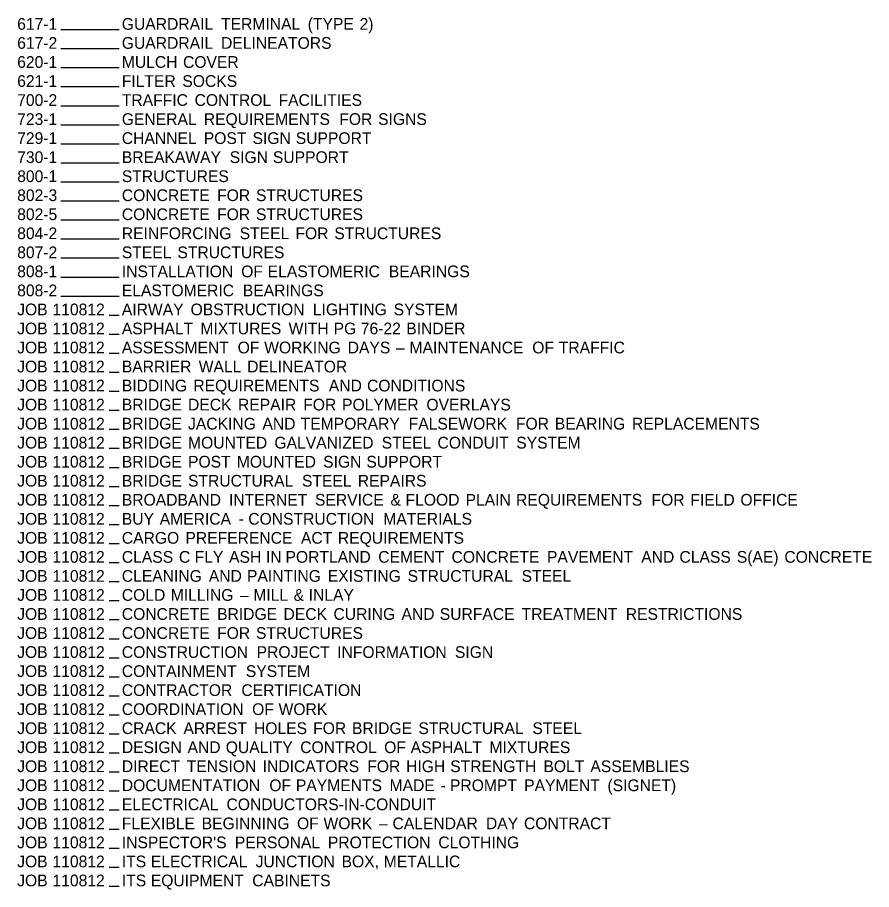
# Model space of a CAD drawing. Extents: x 200 to 2094, y 35 to 1167.
# Drawn here: x 200.8 to 638.5, y 88.4 to 535.1 of the extents above; entities that cross this region are included whole.
import ezdxf

# ---------------------------------------------------------------- set-up
doc = ezdxf.new("R2010")
doc.units = 0
doc.layers.add('Default', color=7, linetype='Continuous')

msp = doc.modelspace()

# ---------------------------------------------------------------- linework, layer by layer
at = {"layer": 'Default'}
for p, q in [((252.93, 528.73), (223.08, 528.73)), ((252.93, 518.98), (223.08, 518.98)), ((252.93, 509.23), (223.08, 509.23)), ((252.93, 499.48), (223.08, 499.48)), ((252.93, 489.73), (223.08, 489.73)), ((252.93, 479.98), (223.08, 479.98)), ((252.93, 470.23), (223.08, 470.23)), ((252.93, 460.48), (223.08, 460.48)), ((252.93, 450.73), (223.08, 450.73)), ((252.93, 440.98), (223.08, 440.98)), ((252.93, 431.23), (223.08, 431.23)), ((252.93, 421.48), (223.08, 421.48)), ((252.93, 411.73), (223.08, 411.73)), ((252.93, 401.98), (223.08, 401.98)), ((252.93, 392.23), (223.08, 392.23)), ((252.93, 382.48), (247.69, 382.48)), ((252.93, 372.73), (247.69, 372.73)), ((252.93, 362.98), (247.69, 362.98)), ((252.93, 353.23), (247.69, 353.23)), ((252.93, 343.48), (247.69, 343.48)), ((252.93, 333.73), (247.69, 333.73)), ((252.93, 323.98), (247.69, 323.98)), ((252.93, 314.23), (247.69, 314.23)), ((252.93, 304.48), (247.69, 304.48)), ((252.93, 294.73), (247.69, 294.73)), ((252.93, 284.98), (247.69, 284.98)), ((252.93, 275.23), (247.69, 275.23)), ((252.93, 265.48), (247.69, 265.48)), ((252.93, 255.73), (247.69, 255.73)), ((252.93, 245.98), (247.69, 245.98)), ((252.93, 236.23), (247.69, 236.23)), ((252.93, 226.48), (247.69, 226.48)), ((252.93, 216.73), (247.69, 216.73)), ((252.93, 206.98), (247.69, 206.98)), ((252.93, 197.23), (247.69, 197.23)), ((252.93, 187.48), (247.69, 187.48)), ((252.93, 177.73), (247.69, 177.73)), ((252.93, 167.98), (247.69, 167.98)), ((252.93, 158.23), (247.69, 158.23)), ((252.93, 148.48), (247.69, 148.48)), ((252.93, 138.73), (247.69, 138.73)), ((252.93, 128.98), (247.69, 128.98)), ((252.93, 119.23), (247.69, 119.23)), ((252.93, 109.48), (247.69, 109.48)), ((252.93, 99.73), (247.69, 99.73)), ((252.93, 89.98), (247.69, 89.98))]:
    msp.add_line(p, q, dxfattribs=at)

# ---------------------------------------------------------------- texts
for s, p in [('617-1', (200.64, 528.79)), ('GUARDRAIL', (254.26, 528.79)), (' TERMINAL', (302.88, 528.79)), (' (TYPE', (347.3, 528.79)), (' 2)', (373.87, 528.79)), ('617-2', (200.64, 519.04)), ('GUARDRAIL', (254.26, 519.04)), (' DELINEATORS', (302.88, 519.04)), ('620-1', (200.64, 509.29)), ('MULCH', (254.26, 509.29)), (' COVER', (283.39, 509.29)), ('621-1', (200.64, 499.54)), ('FILTER', (254.26, 499.54)), (' SOCKS', (283.03, 499.54)), ('700-2', (200.64, 489.79)), ('TRAFFIC', (254.26, 489.79)), (' CONTROL', (289.33, 489.79)), (' FACILITIES', (332.35, 489.79)), ('723-1', (200.64, 480.04)), ('GENERAL', (254.26, 480.04)), (' REQUIREMENTS', (294.04, 480.04)), (' FOR', (363.47, 480.04)), (' SIGNS', (383.38, 480.04)), ('729-1', (200.64, 470.29)), ('CHANNEL', (254.26, 470.29)), (' POST', (294.03, 470.29)), (' SIGN', (319.02, 470.29)), (' SUPPORT', (341.16, 470.29)), ('730-1', (200.64, 460.54)), ('BREAKAWAY', (254.26, 460.54)), (' SIGN', (307.32, 460.54)), (' SUPPORT', (329.45, 460.54)), ('800-1', (200.64, 450.79)), ('STRUCTURES', (254.26, 450.79)), ('802-3', (200.64, 441.04)), ('CONCRETE', (254.26, 441.04)), (' FOR', (300.86, 441.04)), (' STRUCTURES', (320.78, 441.04)), ('802-5', (200.64, 431.29)), ('CONCRETE', (254.26, 431.29)), (' FOR', (300.86, 431.29)), (' STRUCTURES', (320.78, 431.29)), ('804-2', (200.64, 421.54)), ('REINFORCING', (254.26, 421.54)), (' STEEL', (312.42, 421.54)), (' FOR', (341.02, 421.54)), (' STRUCTURES', (360.93, 421.54)), ('807-2', (200.64, 411.79)), ('STEEL', (254.26, 411.79)), (' STRUCTURES', (280.53, 411.79)), ('808-1', (200.64, 402.04)), ('INSTALLATION', (254.26, 402.04)), (' OF', (313.21, 402.04)), (' ELASTOMERIC', (326.79, 402.04)), (' BEARINGS', (388.88, 402.04)), ('808-2', (200.64, 392.29)), ('ELASTOMERIC', (254.26, 392.29)), (' BEARINGS', (314.03, 392.29)), ('JOB', (200.64, 382.54)), (' 110812', (216.5, 382.54)), ('AIRWAY', (254.26, 382.54)), (' OBSTRUCTION', (287.27, 382.54)), (' LIGHTING', (349.93, 382.54)), (' SYSTEM', (391.33, 382.54)), ('JOB', (200.64, 372.79)), (' 110812', (216.5, 372.79)), ('ASPHALT', (254.26, 372.79)), (' MIXTURES', (292.3, 372.79)), (' WITH', (337.51, 372.79)), (' PG', (360.58, 372.79)), (' 76-22', (374.5, 372.79)), (' BINDER', (397.81, 372.79)), ('JOB', (200.64, 363.04)), (' 110812', (216.5, 363.04)), ('ASSESSMENT', (254.26, 363.04)), (' OF', (311.4, 363.04)), (' WORKING', (324.99, 363.04)), (' DAYS', (367.78, 363.04)), (' MAINTENANCE', (399.47, 363.04)), (' OF', (462.37, 363.04)), (' TRAFFIC', (475.96, 363.04)), ('–', (394.83, 363.04)), ('JOB', (200.64, 353.29)), (' 110812', (216.5, 353.29)), ('BARRIER', (254.26, 353.29)), (' WALL', (291.42, 353.29)), (' DELINEATOR', (316.28, 353.29)), ('JOB', (200.64, 343.54)), (' 110812', (216.5, 343.54)), ('BIDDING', (254.26, 343.54)), (' REQUIREMENTS', (288.67, 343.54)), (' AND', (358.11, 343.54)), (' CONDITIONS', (377.69, 343.54)), ('JOB', (200.64, 333.79)), (' 110812', (216.5, 333.79)), ('BRIDGE', (254.26, 333.79)), (' DECK', (285.96, 333.79)), (' REPAIR', (311.56, 333.79)), (' FOR', (344.99, 333.79)), (' POLYMER', (364.91, 333.79)), (' OVERLAYS', (408.12, 333.79)), ('JOB', (200.64, 324.04)), (' 110812', (216.5, 324.04)), ('BRIDGE', (254.26, 324.04)), (' JACKING', (285.96, 324.04)), (' AND', (324.1, 324.04)), (' TEMPORARY', (343.68, 324.04)), (' FALSEWORK', (399.05, 324.04)), (' FOR', (454.01, 324.04)), (' BEARING', (473.92, 324.04)), (' REPLACEMENTS', (513.46, 324.04)), ('JOB', (200.64, 314.29)), (' 110812', (216.5, 314.29)), ('BRIDGE', (254.26, 314.29)), (' MOUNTED', (285.96, 314.29)), (' GALVANIZED', (330.22, 314.29)), (' STEEL', (385.22, 314.29)), (' CONDUIT', (413.81, 314.29)), (' SYSTEM', (454.16, 314.29)), ('JOB', (200.64, 304.54)), (' 110812', (216.5, 304.54)), ('BRIDGE', (254.26, 304.54)), (' POST', (285.96, 304.54)), (' MOUNTED', (310.95, 304.54)), (' SIGN', (355.21, 304.54)), (' SUPPORT', (377.35, 304.54)), ('JOB', (200.64, 294.79)), (' 110812', (216.5, 294.79)), ('BRIDGE', (254.26, 294.79)), (' STRUCTURAL', (285.96, 294.79)), (' STEEL', (344.35, 294.79)), (' REPAIRS', (372.95, 294.79)), ('JOB', (200.64, 285.04)), (' 110812', (216.5, 285.04)), ('BROADBAND', (254.26, 285.04)), (' INTERNET', (306.93, 285.04)), (' SERVICE', (351.01, 285.04)), (' &', (389.7, 285.04)), (' FLOOD', (397.43, 285.04)), (' PLAIN', (428.19, 285.04)), (' REQUIREMENTS', (454.06, 285.04)), (' FOR', (523.49, 285.04)), (' FIELD', (543.4, 285.04)), (' OFFICE', (569.04, 285.04)), ('JOB', (200.64, 275.29)), (' 110812', (216.5, 275.29)), ('BUY', (254.26, 275.29)), (' AMERICA', (271.44, 275.29)), (' -', (311.98, 275.29)), (' CONSTRUCTION', (316.84, 275.29)), (' MATERIALS', (386.02, 275.29)), ('JOB', (200.64, 265.54)), (' 110812', (216.5, 265.54)), ('CARGO', (254.26, 265.54)), (' PREFERENCE', (284.63, 265.54)), (' ACT', (343.82, 265.54)), (' REQUIREMENTS', (362.75, 265.54)), ('JOB', (200.64, 255.79)), (' 110812', (216.5, 255.79)), ('CLASS', (254.26, 255.79)), (' C', (281.32, 255.79)), (' FLY', (289.37, 255.79)), (' ASH', (307.01, 255.79)), (' IN', (325.9, 255.79)), (' PORTLAND', (335.92, 255.79)), (' CEMENT', (383.45, 255.79)), (' CONCRETE', (421.01, 255.79)), (' PAVEMENT', (469.94, 255.79)), (' AND', (518.23, 255.79)), (' CLASS', (537.81, 255.79)), (' S(AE)', (567.19, 255.79)), (' CONCRETE', (591.58, 255.79)), ('JOB', (200.64, 246.04)), (' 110812', (216.5, 246.04)), ('CLEANING', (254.26, 246.04)), (' AND', (296.6, 246.04)), (' PAINTING', (316.18, 246.04)), (' EXISTING', (357.58, 246.04)), (' STRUCTURAL', (398.51, 246.04)), (' STEEL', (456.9, 246.04)), ('JOB', (200.64, 236.29)), (' 110812', (216.5, 236.29)), ('COLD', (254.26, 236.29)), (' MILLING', (277.11, 236.29)), (' MILL', (319.41, 236.29)), (' &', (340.07, 236.29)), (' INLAY', (347.8, 236.29)), ('–', (314.77, 236.29)), ('JOB', (200.64, 226.54)), (' 110812', (216.5, 226.54)), ('CONCRETE', (254.26, 226.54)), (' BRIDGE', (300.86, 226.54)), (' DECK', (334.89, 226.54)), (' CURING', (360.49, 226.54)), (' AND', (395.36, 226.54)), (' SURFACE', (414.95, 226.54)), (' TREATMENT', (456.89, 226.54)), (' RESTRICTIONS', (510.29, 226.54)), ('JOB', (200.64, 216.79)), (' 110812', (216.5, 216.79)), ('CONCRETE', (254.26, 216.79)), (' FOR', (300.86, 216.79)), (' STRUCTURES', (320.78, 216.79)), ('JOB', (200.64, 207.04)), (' 110812', (216.5, 207.04)), ('CONSTRUCTION', (254.26, 207.04)), (' PROJECT', (321.11, 207.04)), (' INFORMATION', (362.4, 207.04)), (' SIGN', (422.73, 207.04)), ('JOB', (200.64, 197.29)), (' 110812', (216.5, 197.29)), ('CONTAINMENT', (254.26, 197.29)), (' SYSTEM', (315.58, 197.29)), ('JOB', (200.64, 187.54)), (' 110812', (216.5, 187.54)), ('CONTRACTOR', (254.26, 187.54)), (' CERTIFICATION', (313.3, 187.54)), ('JOB', (200.64, 177.79)), (' 110812', (216.5, 177.79)), ('COORDINATION', (254.26, 177.79)), (' OF', (318.79, 177.79)), (' WORK', (332.37, 177.79)), ('JOB', (200.64, 168.04)), (' 110812', (216.5, 168.04)), ('CRACK', (254.26, 168.04)), (' ARREST', (283.6, 168.04)), (' HOLES', (319.76, 168.04)), (' FOR', (350.08, 168.04)), (' BRIDGE', (369.99, 168.04)), (' STRUCTURAL', (404.01, 168.04)), (' STEEL', (462.41, 168.04)), ('JOB', (200.64, 158.29)), (' 110812', (216.5, 158.29)), ('DESIGN', (254.26, 158.29)), (' AND', (285.72, 158.29)), (' QUALITY', (305.3, 158.29)), (' CONTROL', (343.44, 158.29)), (' OF', (386.46, 158.29)), (' ASPHALT', (400.05, 158.29)), (' MIXTURES', (440.41, 158.29)), ('JOB', (200.64, 148.54)), (' 110812', (216.5, 148.54)), ('DIRECT', (254.26, 148.54)), (' TENSION', (285.3, 148.54)), (' INDICATORS', (324.21, 148.54)), (' FOR', (377.8, 148.54)), (' HIGH', (397.71, 148.54)), (' STRENGTH', (420.32, 148.54)), (' BOLT', (468.09, 148.54)), (' ASSEMBLIES', (492.15, 148.54)), ('JOB', (200.64, 138.79)), (' 110812', (216.5, 138.79)), ('DOCUMENTATION', (254.26, 138.79)), (' OF', (327.63, 138.79)), (' PAYMENTS', (341.22, 138.79)), (' MADE', (389.24, 138.79)), (' PROMPT', (420.2, 138.79)), (' PAYMENT', (458.22, 138.79)), (' (SIGNET)', (500.91, 138.79)), (' -', (415.34, 138.79)), ('JOB', (200.64, 129.04)), (' 110812', (216.5, 129.04)), ('ELECTRICAL', (254.26, 129.04)), (' CONDUCTORS-IN-CONDUIT', (305.68, 129.04)), ('JOB', (200.64, 119.29)), (' 110812', (216.5, 119.29)), ('FLEXIBLE', (254.26, 119.29)), (' BEGINNING', (292.96, 119.29)), (' OF', (341.81, 119.29)), (' WORK', (355.39, 119.29)), (' CALENDAR', (390.75, 119.29)), (' DAY', (438.63, 119.29)), (' CONTRACT', (458.13, 119.29)), ('–', (386.11, 119.29)), ('JOB', (200.64, 109.54)), (' 110812', (216.5, 109.54)), ("INSPECTOR'S", (254.26, 109.54)), (' PERSONAL', (309.93, 109.54)), (' PROTECTION', (357.63, 109.54)), (' CLOTHING', (414.23, 109.54)), ('JOB', (200.64, 99.79)), (' 110812', (216.5, 99.79)), ('ITS', (254.26, 99.79)), (' ELECTRICAL', (266.87, 99.79)), (' JUNCTION', (320.61, 99.79)), (' BOX,', (364.64, 99.79)), (' METALLIC', (386.25, 99.79)), ('JOB', (200.64, 90.04)), (' 110812', (216.5, 90.04)), ('ITS', (254.26, 90.04)), (' EQUIPMENT', (266.87, 90.04)), (' CABINETS', (318.87, 90.04))]:
    msp.add_text(s, height=6, dxfattribs=at).set_placement(p)

doc.saveas('drawing.dxf')
